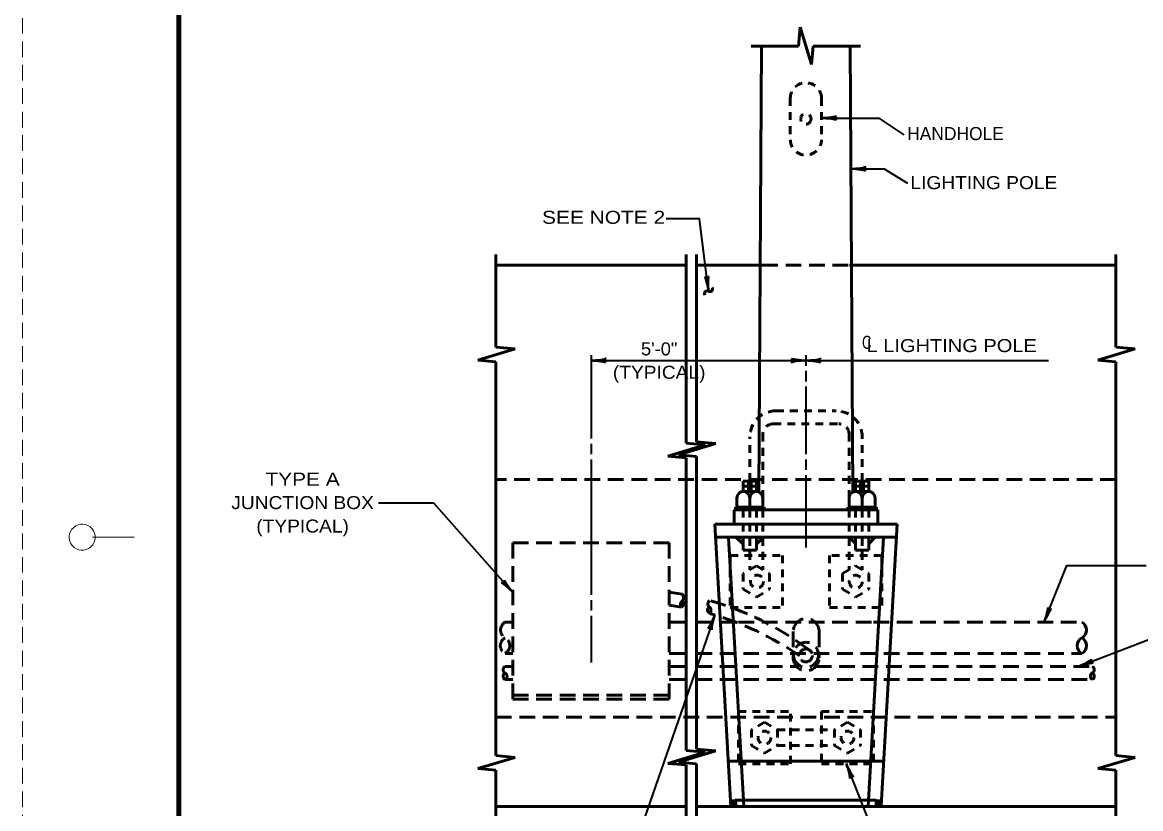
# Model space of a CAD drawing. Extents: x -1 to 679, y 0 to 440.
# Drawn here: x -1.1 to 213.6, y 85.5 to 236.4 of the extents above; entities that cross this region are included whole.
import ezdxf
from ezdxf.enums import TextEntityAlignment as Align

# ---------------------------------------------------------------- set-up
doc = ezdxf.new("R2010")
doc.units = 0
doc.linetypes.add('MEDIUM_DASHED', pattern=[4.5, 3, -1.5])
doc.linetypes.add('SHORT_DASHED', pattern=[2.7, 1.5, -1.2])
doc.layers.add('1', color=7, linetype='Continuous', lineweight=35)
doc.layers.add('61', color=7, linetype='Continuous', lineweight=35)

msp = doc.modelspace()

# ---------------------------------------------------------------- linework, layer by layer
at = {"layer": '1', "linetype": 'MEDIUM_DASHED', "lineweight": 13}
msp.add_line((-0.995, 439.78), (-1.055, -0.26), dxfattribs=at)
at = {"layer": '1', "lineweight": 53}
for p, q in [((147.976, 231.85), (148.299, 235.542)), ((150.461, 228.374), (148.299, 235.542)), ((138.87, 231.85), (147.976, 231.85)), ((140.87, 231.85), (140.367, 146.261)), ((150.461, 228.374), (150.765, 231.85)), ((150.765, 231.85), (159.87, 231.85)), ((157.87, 231.85), (158.374, 146.237)), ((89.87, 191.85), (89.87, 174.078)), ((126.37, 155.639), (126.37, 191.85)), ((128.37, 155.889), (128.37, 191.85)), ((208.87, 191.85), (208.87, 174.078)), ((89.87, 189.85), (126.37, 189.85)), ((128.37, 189.85), (140.995, 189.85)), ((157.745, 189.85), (208.87, 189.85)), ((89.87, 174.078), (93.562, 173.756)), ((208.87, 174.078), (212.562, 173.756)), ((86.394, 171.594), (93.562, 173.756)), ((205.394, 171.594), (212.562, 173.756)), ((86.394, 171.594), (89.87, 171.29)), ((89.87, 171.29), (89.87, 95.639)), ((205.394, 171.594), (208.87, 171.29)), ((208.87, 171.29), (208.87, 95.639)), ((122.894, 153.154), (130.062, 155.316)), ((124.894, 153.404), (132.062, 155.566)), ((126.37, 155.639), (130.062, 155.316)), ((128.37, 155.889), (132.062, 155.566)), ((122.894, 153.154), (126.37, 152.85)), ((124.894, 153.404), (128.37, 153.1)), ((126.37, 152.85), (126.37, 96.639)), ((128.37, 153.1), (128.37, 96.889)), ((137.363, 146.367), (137.363, 148.367)), ((139.87, 148.367), (137.363, 148.367)), ((139.87, 148.367), (139.87, 146.367)), ((158.87, 148.366), (161.43, 148.367)), ((158.87, 148.366), (158.87, 146.366)), ((161.43, 146.367), (161.43, 148.367)), ((139.87, 147.367), (137.363, 147.367)), ((137.363, 146.367), (139.87, 146.367)), ((137.363, 146.367), (139.87, 146.367)), ((139.12, 147.867), (138.113, 147.867)), ((139.12, 146.867), (138.113, 146.867)), ((158.87, 146.366), (161.43, 146.367)), ((158.87, 146.366), (161.43, 146.367)), ((158.871, 147.366), (161.43, 147.367)), ((159.62, 147.866), (160.68, 147.867)), ((159.621, 146.866), (160.681, 146.867)), ((136.113, 145.141), (136.113, 143.35)), ((138.613, 145.141), (138.613, 143.35)), ((141.113, 145.141), (141.113, 143.35)), ((157.68, 145.141), (157.68, 143.35)), ((160.18, 145.141), (160.18, 143.35)), ((162.68, 145.141), (162.68, 143.35)), ((135.613, 142.85), (142.363, 142.85)), ((135.613, 142.85), (135.613, 140.1)), ((135.863, 143.35), (141.363, 143.35)), ((135.863, 143.35), (135.863, 142.85)), ((141.363, 143.35), (141.363, 142.85)), ((142.363, 142.85), (156.43, 142.85)), ((156.43, 142.85), (163.18, 142.85)), ((157.43, 143.35), (162.93, 143.35)), ((157.43, 143.35), (157.43, 142.85)), ((162.93, 143.35), (162.93, 142.85)), ((163.18, 142.85), (163.18, 140.1)), ((131.862, 140.1), (166.931, 140.1)), ((131.862, 140.1), (134.966, 85.85)), ((132.005, 137.6), (138.363, 137.6)), ((134.512, 137.543), (137.465, 85.936)), ((137.363, 137.6), (137.363, 135.1)), ((138.363, 137.6), (142.12, 137.6)), ((139.87, 137.6), (139.87, 135.1)), ((158.87, 135.1), (158.87, 137.6)), ((164.281, 137.543), (161.327, 85.936)), ((161.43, 137.6), (161.43, 135.1)), ((137.363, 135.1), (139.87, 135.1)), ((158.87, 135.1), (161.43, 135.1)), ((123.12, 127.011), (125.609, 126.62)), ((123.12, 124.511), (125.499, 124.14)), ((126.37, 96.639), (130.062, 96.316)), ((128.37, 96.889), (132.062, 96.566)), ((86.394, 93.154), (93.562, 95.316)), ((89.87, 95.639), (93.562, 95.316)), ((122.894, 94.154), (130.062, 96.316)), ((124.894, 94.404), (132.062, 96.566)), ((134.466, 94.6), (164.327, 94.6)), ((205.394, 93.154), (212.562, 95.316)), ((208.87, 95.639), (212.562, 95.316)), ((86.394, 93.154), (89.87, 92.85)), ((89.87, 92.85), (89.87, 76.85)), ((122.894, 94.154), (126.37, 93.85)), ((124.894, 94.404), (128.37, 94.1)), ((126.37, 93.85), (126.37, 76.85)), ((128.37, 94.1), (128.37, 76.85)), ((205.394, 93.154), (208.87, 92.85)), ((208.87, 92.85), (208.87, 76.85)), ((134.912, 87.101), (134.984, 85.851)), ((134.944, 87.103), (135.016, 85.853)), ((134.963, 87.104), (135.034, 85.854)), ((134.981, 87.105), (135.052, 85.855)), ((134.998, 87.1), (134.998, 85.85)), ((135.004, 87.1), (135.004, 85.85)), ((135.017, 87.1), (135.017, 85.85)), ((135.041, 87.1), (135.041, 85.85)), ((135.041, 87.1), (135.041, 85.85)), ((135.053, 87.1), (135.053, 85.85)), ((135.053, 87.1), (135.053, 85.85)), ((135.072, 87.1), (135.072, 85.85)), ((135.078, 87.1), (135.078, 85.85)), ((135.09, 87.1), (135.09, 85.85)), ((135.102, 87.1), (135.102, 85.85)), ((135.114, 87.1), (135.114, 85.85)), ((135.127, 87.1), (135.127, 85.85)), ((135.139, 87.1), (135.139, 85.85)), ((135.139, 87.1), (135.139, 85.85)), ((135.145, 87.1), (135.145, 85.85)), ((135.151, 87.1), (135.151, 85.85)), ((135.163, 87.1), (135.163, 85.85)), ((135.169, 87.1), (135.169, 85.85)), ((135.169, 87.1), (135.169, 85.85)), ((135.169, 87.1), (135.169, 85.85)), ((135.194, 87.1), (135.194, 85.85)), ((135.206, 87.1), (135.206, 85.85)), ((135.212, 87.1), (135.212, 85.85)), ((135.212, 87.1), (135.212, 85.85)), ((135.231, 87.1), (135.231, 85.85)), ((135.237, 87.1), (135.237, 85.85)), ((135.237, 87.1), (135.237, 85.85)), ((135.249, 87.1), (135.249, 85.85)), ((135.261, 87.1), (135.261, 85.85)), ((135.261, 87.1), (135.261, 85.85)), ((135.286, 87.1), (135.286, 85.85)), ((135.304, 87.1), (135.304, 85.85)), ((135.304, 87.1), (135.304, 85.85)), ((135.322, 87.1), (135.322, 85.85)), ((135.347, 87.1), (135.347, 85.85)), ((135.359, 87.1), (135.359, 85.85)), ((135.359, 87.1), (135.359, 85.85)), ((135.377, 87.1), (135.377, 85.85)), ((135.408, 87.1), (135.408, 85.85)), ((135.414, 87.1), (135.414, 85.85)), ((135.432, 87.1), (135.432, 85.85)), ((135.457, 87.1), (135.457, 85.85)), ((135.475, 87.1), (135.475, 85.85)), ((135.475, 87.1), (135.475, 85.85)), ((135.481, 87.1), (135.481, 85.85)), ((135.481, 87.1), (135.481, 85.85)), ((135.487, 87.1), (135.487, 85.85)), ((135.518, 87.1), (135.518, 85.85)), ((135.536, 87.1), (135.536, 85.85)), ((135.542, 87.1), (135.542, 85.85)), ((135.561, 87.1), (135.561, 85.85)), ((135.573, 87.1), (135.573, 85.85)), ((135.585, 87.1), (135.585, 85.85)), ((135.61, 87.1), (135.61, 85.85)), ((135.616, 87.1), (135.616, 85.85)), ((135.634, 87.1), (135.634, 85.85)), ((135.659, 87.1), (135.659, 85.85)), ((135.665, 87.1), (135.665, 85.85)), ((135.665, 87.1), (135.665, 85.85)), ((135.677, 87.1), (135.677, 85.85)), ((135.689, 87.1), (135.689, 85.85)), ((135.707, 87.1), (135.707, 85.85)), ((135.714, 87.1), (135.714, 85.85)), ((135.72, 87.1), (135.72, 85.85)), ((135.732, 87.1), (135.732, 85.85)), ((135.738, 87.1), (135.738, 85.85)), ((135.762, 87.1), (135.762, 85.85)), ((135.769, 87.1), (135.769, 85.85)), ((135.775, 87.1), (135.775, 85.85)), ((135.781, 87.1), (135.781, 85.85)), ((135.799, 87.1), (135.799, 85.85)), ((135.805, 87.1), (135.805, 85.85)), ((135.824, 87.1), (135.824, 85.85)), ((135.836, 87.1), (135.836, 85.85)), ((135.842, 87.1), (135.842, 85.85)), ((135.854, 87.1), (135.854, 85.85)), ((135.873, 87.1), (135.873, 85.85)), ((135.879, 87.1), (135.879, 85.85)), ((135.879, 87.1), (135.879, 85.85)), ((135.879, 87.1), (135.879, 85.85)), ((135.903, 87.1), (135.903, 85.85)), ((135.903, 87.1), (135.903, 85.85)), ((162.885, 87.1), (162.885, 85.85)), ((162.896, 87.1), (162.896, 85.85)), ((162.917, 87.1), (162.917, 85.85)), ((162.922, 87.1), (162.922, 85.85)), ((162.944, 87.1), (162.944, 85.85)), ((162.959, 87.1), (162.959, 85.85)), ((162.959, 87.1), (162.959, 85.85)), ((162.965, 87.1), (162.965, 85.85)), ((162.97, 87.1), (162.97, 85.85)), ((162.975, 87.1), (162.975, 85.85)), ((162.975, 87.1), (162.975, 85.85)), ((162.991, 87.1), (162.991, 85.85)), ((163.018, 87.1), (163.018, 85.85)), ((163.018, 87.1), (163.018, 85.85)), ((163.023, 87.1), (163.023, 85.85)), ((163.049, 87.1), (163.049, 85.85)), ((163.06, 87.1), (163.06, 85.85)), ((163.06, 87.1), (163.06, 85.85)), ((163.065, 87.1), (163.065, 85.85)), ((163.076, 87.1), (163.076, 85.85)), ((163.081, 87.1), (163.081, 85.85)), ((163.086, 87.1), (163.086, 85.85)), ((163.092, 87.1), (163.092, 85.85)), ((163.092, 87.1), (163.092, 85.85)), ((163.118, 87.1), (163.118, 85.85)), ((163.134, 87.1), (163.134, 85.85)), ((163.134, 87.1), (163.134, 85.85)), ((163.15, 87.1), (163.15, 85.85)), ((163.155, 87.1), (163.155, 85.85)), ((163.16, 87.1), (163.16, 85.85)), ((163.166, 87.1), (163.166, 85.85)), ((163.166, 87.1), (163.166, 85.85)), ((163.181, 87.1), (163.181, 85.85)), ((163.197, 87.1), (163.197, 85.85)), ((163.208, 87.1), (163.208, 85.85)), ((163.229, 87.1), (163.229, 85.85)), ((163.245, 87.1), (163.245, 85.85)), ((163.25, 87.1), (163.25, 85.85)), ((163.25, 87.1), (163.25, 85.85)), ((163.256, 87.1), (163.256, 85.85)), ((163.261, 87.1), (163.261, 85.85)), ((163.261, 87.1), (163.261, 85.85)), ((163.271, 87.1), (163.271, 85.85)), ((163.287, 87.1), (163.287, 85.85)), ((163.303, 87.1), (163.303, 85.85)), ((163.303, 87.1), (163.303, 85.85)), ((163.324, 87.1), (163.324, 85.85)), ((163.324, 87.1), (163.324, 85.85)), ((163.324, 87.1), (163.324, 85.85)), ((163.335, 87.1), (163.335, 85.85)), ((163.351, 87.1), (163.351, 85.85)), ((163.356, 87.1), (163.356, 85.85)), ((163.382, 87.1), (163.382, 85.85)), ((163.388, 87.1), (163.388, 85.85)), ((163.388, 87.1), (163.388, 85.85)), ((163.398, 87.1), (163.398, 85.85)), ((163.409, 87.1), (163.409, 85.85)), ((163.42, 87.1), (163.42, 85.85)), ((163.43, 87.1), (163.43, 85.85)), ((163.435, 87.1), (163.435, 85.85)), ((163.435, 87.1), (163.435, 85.85)), ((163.435, 87.1), (163.435, 85.85)), ((163.451, 87.1), (163.451, 85.85)), ((163.467, 87.1), (163.467, 85.85)), ((163.472, 87.1), (163.472, 85.85)), ((163.494, 87.1), (163.494, 85.85)), ((163.51, 87.1), (163.51, 85.85)), ((163.51, 87.1), (163.51, 85.85)), ((163.525, 87.1), (163.525, 85.85)), ((163.531, 87.1), (163.531, 85.85)), ((163.531, 87.1), (163.531, 85.85)), ((163.546, 87.1), (163.546, 85.85)), ((163.573, 87.1), (163.573, 85.85)), ((163.589, 87.1), (163.589, 85.85)), ((163.589, 87.1), (163.589, 85.85)), ((163.605, 87.1), (163.605, 85.85)), ((163.61, 87.1), (163.61, 85.85)), ((163.621, 87.1), (163.621, 85.85)), ((163.631, 87.1), (163.631, 85.85)), ((163.647, 87.1), (163.647, 85.85)), ((163.663, 87.1), (163.663, 85.85)), ((163.679, 87.1), (163.679, 85.85)), ((163.679, 87.1), (163.679, 85.85)), ((163.679, 87.1), (163.679, 85.85)), ((163.7, 87.1), (163.7, 85.85)), ((163.716, 87.1), (163.716, 85.85)), ((163.721, 87.1), (163.721, 85.85)), ((163.726, 87.1), (163.726, 85.85)), ((163.732, 87.1), (163.732, 85.85)), ((163.742, 87.1), (163.742, 85.85)), ((163.753, 87.1), (163.753, 85.85)), ((163.753, 87.1), (163.753, 85.85)), ((163.763, 87.1), (163.763, 85.85)), ((163.774, 87.1), (163.774, 85.85)), ((163.779, 87.1), (163.779, 85.85)), ((163.779, 87.1), (163.779, 85.85)), ((163.869, 87.102), (163.797, 85.852)), ((163.876, 87.102), (163.804, 85.852)), ((163.881, 87.101), (163.81, 85.851)), ((163.811, 87.1), (163.811, 85.85)), ((163.889, 87.101), (163.818, 85.851)), ((89.87, 85.85), (126.37, 85.85))]:
    msp.add_line(p, q, dxfattribs=at)
at = {"layer": '1', "linetype": 'SHORT_DASHED', "lineweight": 53}
for p, q in [((146.37, 221.908), (146.37, 213.908)), ((152.37, 221.908), (152.37, 213.908)), ((143.613, 161.85), (155.18, 161.85)), ((143.113, 159.35), (155.68, 159.35)), ((138.613, 148.367), (138.613, 156.85)), ((141.113, 145.141), (141.113, 157.35)), ((157.68, 145.141), (157.68, 157.35)), ((160.18, 148.367), (160.18, 156.85)), ((137.363, 142.85), (137.363, 137.6)), ((138.613, 142.85), (138.613, 131.35)), ((139.87, 142.85), (139.87, 137.6)), ((141.113, 142.85), (141.113, 131.35)), ((157.68, 142.85), (157.68, 131.35)), ((158.87, 142.85), (158.87, 137.6)), ((160.18, 142.85), (160.18, 131.35)), ((161.43, 142.85), (161.43, 137.6)), ((134.863, 134.1), (134.863, 124.1)), ((134.863, 134.1), (144.863, 134.1)), ((144.863, 134.1), (144.863, 124.1)), ((153.93, 134.1), (153.93, 124.1)), ((163.93, 134.1), (153.93, 134.1)), ((163.93, 134.1), (163.93, 124.1)), ((139.863, 132.1), (137.363, 130.6)), ((139.863, 132.1), (142.363, 130.6)), ((137.363, 130.6), (137.363, 127.6)), ((142.363, 130.6), (142.363, 127.6)), ((156.43, 130.6), (156.43, 127.6)), ((161.43, 130.6), (161.43, 127.6)), ((134.863, 124.1), (144.863, 124.1)), ((153.93, 124.1), (163.93, 124.1)), ((136.428, 104.1), (146.428, 104.1)), ((136.428, 104.1), (136.428, 94.1)), ((152.365, 104.1), (162.365, 104.1)), ((152.365, 104.1), (152.365, 94.1)), ((162.365, 104.1), (162.365, 94.1)), ((162.365, 104.1), (162.365, 94.1)), ((141.428, 102.1), (138.928, 100.6)), ((141.428, 102.1), (143.928, 100.6)), ((157.365, 102.1), (154.865, 100.6)), ((157.365, 102.1), (159.865, 100.6)), ((138.928, 100.6), (138.928, 97.6)), ((143.928, 100.6), (143.928, 97.6)), ((143.928, 100.6), (154.865, 100.6)), ((154.865, 100.6), (154.865, 97.6)), ((159.865, 100.6), (159.865, 97.6)), ((143.928, 97.6), (154.865, 97.6)), ((152.365, 94.1), (162.365, 94.1))]:
    msp.add_line(p, q, dxfattribs=at)
at = {"layer": '1', "linetype": 'MEDIUM_DASHED', "lineweight": 53}
for p, q in [((140.995, 189.85), (157.745, 189.85)), ((208.87, 148.689), (89.87, 148.689)), ((93.12, 136.511), (123.12, 136.511)), ((93.12, 136.511), (93.12, 106.511)), ((123.12, 136.511), (123.12, 106.511)), ((93.12, 121.261), (91.62, 121.261)), ((123.12, 121.261), (126.37, 121.261)), ((146.931, 119.45), (146.931, 114.45)), ((151.931, 119.45), (151.931, 114.45)), ((93.12, 115.261), (91.62, 115.261)), ((123.12, 115.261), (126.37, 115.261)), ((128.37, 115.261), (202.351, 115.261)), ((93.12, 112.761), (91.62, 112.761)), ((123.12, 112.761), (126.37, 112.761)), ((128.37, 112.761), (147.588, 112.761)), ((151.275, 112.761), (204.365, 112.761)), ((93.12, 110.261), (91.62, 110.261)), ((123.12, 110.261), (126.37, 110.261)), ((128.37, 110.261), (204.365, 110.261)), ((93.12, 107.261), (123.12, 107.261)), ((93.12, 106.511), (123.12, 106.511)), ((89.87, 103.011), (208.87, 103.011))]:
    msp.add_line(p, q, dxfattribs=at)
at = {"layer": '1'}
for p, q in [((108.12, 172.511), (108.12, 156.511)), ((149.397, 170.511), (149.397, 172.511)), ((149.397, 167.511), (149.397, 169.511)), ((149.397, 153.511), (149.397, 166.511)), ((108.12, 155.511), (108.12, 153.511)), ((108.12, 152.511), (108.12, 126.511)), ((149.397, 150.511), (149.397, 152.511)), ((149.397, 135.6), (149.397, 149.511)), ((108.12, 125.511), (108.12, 123.511)), ((108.12, 122.511), (108.12, 113.511)), ((131.873, 122.636), (113.815, 70.633)), ((134.895, 87.1), (163.898, 87.1))]:
    msp.add_line(p, q, dxfattribs=at)
for points in [[(152.353, 218.071), (163.403, 218.071), (168.202, 214.872)], [(158.009, 208.324), (164.374, 208.324), (168.854, 205.598)], [(130.679, 184.803), (128.977, 198.739), (122.568, 198.739)], [(108.12, 171.511), (149.397, 171.511), (195.95, 171.511)], [(93.12, 126.95), (77.942, 144.114), (67.317, 144.114)], [(195.099, 121.261), (199.457, 132.158), (214.729, 132.158)], [(201.699, 112.761), (216.389, 118.375), (227.345, 118.375)], [(157.137, 94.1), (166.339, 70.633), (176.631, 70.633)]]:
    msp.add_lwpolyline(points, dxfattribs=at)
at = {"layer": '1', "lineweight": 53}
for points in [[(166.931, 140.1), (163.898, 87.1), (163.827, 85.85)], [(142.12, 137.6), (157.87, 137.6), (160.43, 137.6), (166.788, 137.6)], [(128.37, 85.85), (162.897, 85.85), (208.87, 85.85)]]:
    msp.add_lwpolyline(points, dxfattribs=at)
for points in [[(137.301, 137.494), (136.051, 137.494), (137.301, 136.244)], [(139.914, 136.244), (141.164, 137.494), (139.914, 137.494)], [(157.618, 137.596), (158.868, 137.596), (158.868, 136.346)], [(161.451, 137.581), (162.701, 137.581), (161.451, 136.331)], [(162.897, 87.1), (162.897, 85.85), (135.897, 85.85), (135.897, 87.1)]]:
    msp.add_lwpolyline(points, close=True, dxfattribs=at)
at = {"layer": '1', "linetype": 'SHORT_DASHED', "lineweight": 53}
for points in [[(156.43, 130.6), (158.93, 132.1), (161.43, 130.6)], [(137.363, 127.6), (139.863, 126.1), (142.363, 127.6)], [(156.43, 127.6), (158.93, 126.1), (161.43, 127.6)], [(136.428, 94.1), (146.428, 94.1), (146.428, 104.1)], [(138.928, 97.6), (141.428, 96.1), (143.928, 97.6)], [(154.865, 97.6), (157.365, 96.1), (159.865, 97.6)]]:
    msp.add_lwpolyline(points, dxfattribs=at)
at = {"layer": '1', "linetype": 'MEDIUM_DASHED', "lineweight": 53}
msp.add_lwpolyline([(128.37, 121.261), (136.445, 121.261), (162.347, 121.261), (202.351, 121.261)], dxfattribs=at)
at = {"layer": '1', "linetype": 'SHORT_DASHED', "lineweight": 53}
for centre, radius in [((149.37, 217.908), 1), ((139.978, 129.065), 1.25), ((158.957, 129.029), 1.25), ((141.428, 99.1), 1.25), ((157.365, 99.1), 1.25)]:
    msp.add_circle(centre, radius, dxfattribs=at)
at = {"layer": '1', "linetype": 'MEDIUM_DASHED', "lineweight": 53}
for centre, radius in [((149.393, 115.002), 2.4), ((149.376, 114.888), 1.25)]:
    msp.add_circle(centre, radius, dxfattribs=at)
at = {"layer": '1', "linetype": 'SHORT_DASHED', "lineweight": 53}
for centre, radius, start, end in [((149.37, 221.848), 3.001, 1.1523, 178.8477), ((149.37, 213.969), 3.001, 181.1523, 358.8477), ((143.613, 156.85), 5, 90, 180), ((155.18, 156.85), 5, 0, 90), ((143.113, 157.35), 2, 90, 180), ((155.68, 157.35), 2, 0, 90)]:
    msp.add_arc(centre, radius, start, end, dxfattribs=at)
at = {"layer": '1', "lineweight": 53}
for centre, radius, start, end in [((130.421, 184.361), 0.513, 59.71531, 214.28469), ((130.938, 185.246), 0.513, 239.71531, 34.28469), ((137.363, 145.117), 1.25, 90, 178.88668), ((137.363, 145.117), 1.25, 1.11332, 90), ((137.363, 145.117), 1.25, 1.11332, 90), ((139.863, 145.117), 1.25, 89.67156, 178.88668), ((139.863, 145.117), 1.25, 90.32844, 178.88668), ((139.863, 145.117), 1.25, 1.11332, 89.67156), ((158.93, 145.117), 1.25, 92.7125, 178.88668), ((158.93, 145.117), 1.25, 1.11332, 92.7125), ((158.93, 145.117), 1.25, 1.11332, 87.2875), ((161.43, 145.117), 1.25, 90, 178.88668), ((161.43, 145.117), 1.25, 90, 178.88668), ((161.43, 145.117), 1.25, 1.11332, 90), ((126.155, 124.694), 0.845, 125.75502, 221.12003), ((125.016, 124.834), 0.845, 304.87997, 40.24498), ((125.062, 125.976), 0.845, 315.16746, 49.69352), ((131.407, 124.783), 0.845, 130.30648, 224.83254), ((131.176, 123.605), 0.689, 122.29232, 252.58274), ((130.314, 123.501), 0.845, 318.87997, 54.24498), ((201.499, 119.761), 1.725, 299.59893, 60.40107), ((203.136, 116.761), 1.693, 117.62202, 242.37798), ((201.584, 116.761), 1.685, 297.09451, 62.90548), ((204.029, 112.136), 0.71, 298.29957, 61.70043), ((204.696, 110.886), 0.71, 118.29957, 241.70043), ((204.029, 110.886), 0.71, 298.29957, 61.70043)]:
    msp.add_arc(centre, radius, start, end, dxfattribs=at)
at = {"layer": '1', "linetype": 'MEDIUM_DASHED', "lineweight": 53}
for centre, radius, start, end in [((115.599, 70.548), 56.962, 53.08802, 74.45884), ((115.599, 68.048), 56.962, 55.17394, 74.40337), ((92.473, 119.761), 1.725, 119.59892, 240.40107), ((149.431, 119.45), 2.5, 0, 180), ((92.388, 116.761), 1.685, 117.09452, 242.90549), ((90.836, 116.761), 1.693, 297.62202, 62.37798), ((149.431, 114.45), 2.5, 180, 0), ((91.957, 112.136), 0.71, 118.29957, 241.70043), ((91.957, 110.886), 0.71, 118.29957, 241.70043), ((91.29, 110.886), 0.71, 298.29957, 61.70043)]:
    msp.add_arc(centre, radius, start, end, dxfattribs=at)
at = {"layer": '1', "lineweight": 40}
for centre, major_axis, ratio, start_param, end_param in [((153.473, 217.86), (-1.756, 0.176), 0.07063, 3.1407148, 5.41811), ((153.444, 218.347), (-1.786, -0.156), 0.122415, 0.8963533, 3.1415927), ((159.129, 208.113), (-1.756, 0.176), 0.07063, 3.1407148, 5.41811), ((159.1, 208.6), (-1.786, -0.156), 0.122415, 0.8963533, 3.1415927), ((130.273, 185.853), (0.371, -1.754), 0.122415, 0.8963533, 3.1415927), ((130.754, 185.941), (0.039, -1.765), 0.07063, 3.1407148, 5.41811), ((109.212, 171.788), (-1.786, -0.156), 0.122415, 0.8963533, 3.1415927), ((109.212, 171.788), (-1.786, -0.156), 0.122415, 0.8963533, 3.1415927), ((148.276, 171.723), (1.756, -0.176), 0.07063, 3.1407148, 5.41811), ((148.276, 171.723), (1.756, -0.176), 0.07063, 3.1407148, 5.41811), ((150.488, 171.788), (-1.786, -0.156), 0.122415, 0.8963533, 3.1415927), ((109.241, 171.3), (-1.756, 0.176), 0.07063, 3.1407148, 5.41811), ((109.241, 171.3), (-1.756, 0.176), 0.07063, 3.1407148, 5.41811), ((148.305, 171.235), (1.786, 0.156), 0.122415, 0.8963533, 3.1415927), ((148.305, 171.235), (1.786, 0.156), 0.122415, 0.8963533, 3.1415927), ((150.517, 171.3), (-1.756, 0.176), 0.07063, 3.1407148, 5.41811), ((92.191, 127.584), (1.3, -1.234), 0.122415, 0.8963533, 3.1415927), ((92.537, 127.929), (-1.032, 1.432), 0.07063, 6.2823074, 8.5597026), ((131.306, 121.647), (-0.742, -1.602), 0.07063, 6.2823074, 8.5597026), ((131.776, 121.514), (0.438, 1.738), 0.122415, 0.8963533, 3.1415927), ((195.248, 122.377), (-0.518, -1.716), 0.122415, 0.8963533, 3.1415927), ((195.712, 122.223), (0.815, 1.566), 0.07063, 6.2823074, 8.5597026), ((202.62, 113.409), (-1.612, -0.783), 0.122415, 0.8963533, 3.1415927), ((202.821, 112.964), (1.703, 0.463), 0.07063, 6.2823074, 8.5597026), ((157.349, 92.98), (0.478, -1.699), 0.07063, 6.2823074, 8.5597026), ((157.793, 93.185), (-0.797, 1.605), 0.122415, 0.8963533, 3.1415927)]:
    msp.add_ellipse(centre, major_axis=major_axis, ratio=ratio, start_param=start_param, end_param=end_param, dxfattribs=at)
at = {"layer": '61', "lineweight": 13}
msp.add_line((12.425, 137.6), (20.425, 137.6), dxfattribs=at)
at = {"layer": '61', "lineweight": 158}
msp.add_lwpolyline([(668.045, 429.78), (29.005, 429.78), (29.005, 9.76)], dxfattribs=at)
at = {"layer": '61', "lineweight": 13}
msp.add_arc((10.423, 137.581), 2.5, 322.67175, 321.71615, dxfattribs=at)

# ---------------------------------------------------------------- texts
at = {"layer": '1'}
msp.add_text('HANDHOLE', height=2.5, dxfattribs=at).set_placement((168.817, 213.845))
for s, width, p in [('LIGHTING POLE', 1.1, (169.445, 204.42)), ('SEE NOTE 2', 1.2, (98.722, 197.761)), ('C', 0.75, (160.149, 173.76)), ('L LIGHTING POLE', 1.15, (161.028, 173.132))]:
    msp.add_text(s, height=2.5, dxfattribs=dict(at, width=width)).set_placement(p)
for s, width, p in [('5\'-0"', 1.05, (121.208, 172.498)), ('(TYPICAL)', 1.1, (121.208, 167.998)), ('TYPE A', 1.2, (52.746, 147.48)), ('JUNCTION BOX', 1.1, (52.746, 142.98)), ('(TYPICAL)', 1.1, (52.746, 138.48))]:
    msp.add_text(s, height=2.5, dxfattribs=dict(at, width=width)).set_placement(p, align=Align.CENTER)

doc.saveas('drawing.dxf')
